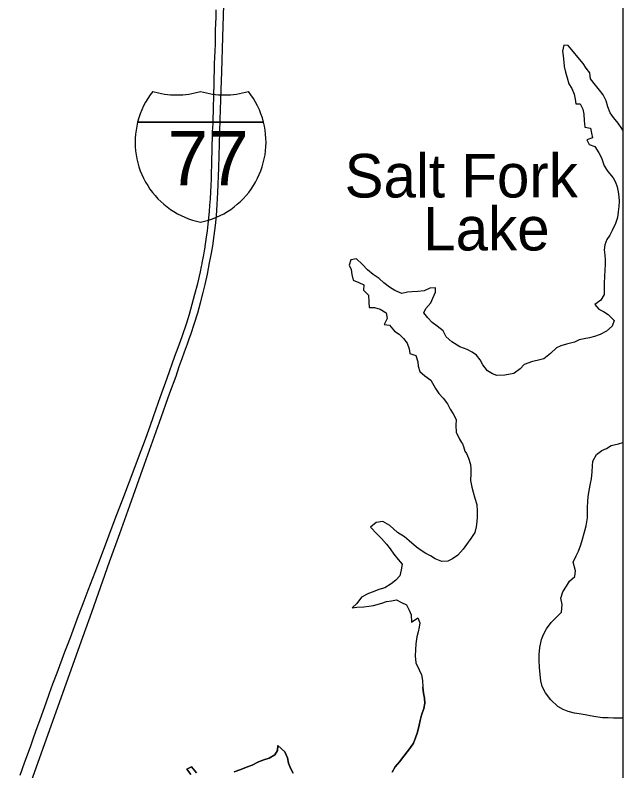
# Model space of a CAD drawing. Extents: x -12.1 to 34, y 0 to 22.
# Drawn here: x -5.676 to -4.438, y 15.867 to 17.405 of the extents above; entities that cross this region are included whole.
import ezdxf

# ---------------------------------------------------------------- set-up
doc = ezdxf.new("R2010")
doc.units = 0
for name, color, linetype in [('GM_X_Interstate_Route', 7, 'Continuous'), ('GM_X_Interstate_Shield', 7, 'Continuous'), ('GM_X_Major_Lake', 7, 'Continuous'), ('GM_X_Major_Lake_Text', 7, 'Continuous'), ('SH_Text', 7, 'Continuous')]:
    doc.layers.add(name, color=color, linetype=linetype)

msp = doc.modelspace()

# ---------------------------------------------------------------- linework, layer by layer
at = {"layer": 'GM_X_Interstate_Route'}
for points in [[(-5.6699, 15.7681), (-5.5912, 15.9891), (-5.5378, 16.1389), (-5.5195, 16.1898), (-5.4833, 16.2919), (-5.4626, 16.3494), (-5.4421, 16.407), (-5.4123, 16.491), (-5.3814, 16.5764), (-5.3605, 16.6357), (-5.3481, 16.6702), (-5.3414, 16.6895), (-5.3354, 16.7059), (-5.3306, 16.7197), (-5.3249, 16.7355), (-5.3213, 16.7457), (-5.3182, 16.7548), (-5.3105, 16.778), (-5.304, 16.7991), (-5.2982, 16.8193), (-5.2928, 16.8401), (-5.2889, 16.8565), (-5.2843, 16.8776), (-5.2797, 16.9004), (-5.2759, 16.9204), (-5.2734, 16.9353), (-5.2703, 16.956), (-5.2678, 16.9762), (-5.2658, 16.9965), (-5.264, 17.0191), (-5.2627, 17.0435), (-5.2608, 17.0936), (-5.2579, 17.1913), (-5.256, 17.2525), (-5.255, 17.2891), (-5.2531, 17.3601), (-5.251, 17.4259)], [(-5.6651, 15.8581), (-5.6563, 15.8828), (-5.6496, 15.9014), (-5.6445, 15.9157), (-5.6387, 15.9321), (-5.6332, 15.9475), (-5.6248, 15.971), (-5.6127, 16.005), (-5.6056, 16.0248), (-5.5987, 16.0439), (-5.5904, 16.0663), (-5.5742, 16.1087), (-5.5692, 16.1223), (-5.5632, 16.1381), (-5.5577, 16.1529), (-5.5464, 16.1828), (-5.5404, 16.1986), (-5.5351, 16.2128), (-5.5268, 16.2345), (-5.5129, 16.271), (-5.5, 16.3047), (-5.4847, 16.3449), (-5.4718, 16.3793), (-5.4546, 16.425), (-5.4332, 16.4807), (-5.4222, 16.5097), (-5.4125, 16.5362), (-5.4009, 16.5678), (-5.3939, 16.5877), (-5.3794, 16.6288), (-5.3663, 16.6656), (-5.3502, 16.7105), (-5.3438, 16.7282), (-5.3357, 16.7509), (-5.3263, 16.7785), (-5.3206, 16.7963), (-5.3149, 16.8161), (-5.3096, 16.8368), (-5.3039, 16.8586), (-5.2986, 16.8823), (-5.2962, 16.8931), (-5.295, 16.8982), (-5.2946, 16.9005), (-5.2929, 16.9103), (-5.2916, 16.9171), (-5.2901, 16.9251), (-5.2896, 16.9286), (-5.2881, 16.9384), (-5.2859, 16.9528), (-5.2843, 16.9655), (-5.2827, 16.9789), (-5.2815, 16.9922), (-5.2802, 17.005), (-5.2793, 17.0172), (-5.2782, 17.0305), (-5.2773, 17.0451), (-5.2768, 17.0579), (-5.2761, 17.0718), (-5.2759, 17.0852), (-5.2753, 17.0986), (-5.2751, 17.1132), (-5.2745, 17.1259), (-5.2743, 17.1405), (-5.2737, 17.1539), (-5.2735, 17.1673), (-5.2727, 17.1835), (-5.2724, 17.1952), (-5.2721, 17.2091), (-5.2715, 17.2225), (-5.2713, 17.2336), (-5.2709, 17.247), (-5.2705, 17.2604), (-5.2702, 17.2772), (-5.2697, 17.2912), (-5.2695, 17.3057), (-5.2689, 17.3191), (-5.2686, 17.3319), (-5.268, 17.3459), (-5.2676, 17.3599), (-5.2674, 17.3733), (-5.2668, 17.3884), (-5.2667, 17.4), (-5.2662, 17.4157)]]:
    msp.add_lwpolyline(points, dxfattribs=at)
at = {"layer": 'GM_X_Interstate_Shield'}
for p, q in [((-5.4262, 17.1871), (-5.17, 17.1871)), ((-5.17, 17.1871), (-5.4262, 17.1871)), ((-5.17, 17.1871), (-5.4262, 17.1871))]:
    msp.add_line(p, q, dxfattribs=at)
for centre, start, end in [((-5.2648, 17.1463), 141.669, 165.8066), ((-5.3468, 17.4087), 253.0091, 286.9909), ((-5.2495, 17.4087), 253.0091, 286.9909), ((-5.3314, 17.1463), 14.1934, 38.331), ((-5.2648, 17.1463), 165.8066, 258.463), ((-5.3314, 17.1463), 281.537, 14.1934)]:
    msp.add_arc(centre, 0.1665, start, end, dxfattribs=at)
at = {"layer": 'GM_X_Major_Lake'}
for points in [[(-4.4383, 17.1708), (-4.4405, 17.1738), (-4.4481, 17.1848), (-4.4574, 17.1961), (-4.4642, 17.206), (-4.4689, 17.218), (-4.4722, 17.2301), (-4.4787, 17.2425), (-4.4859, 17.2521), (-4.4941, 17.2623), (-4.5042, 17.2747), (-4.5053, 17.2875), (-4.5132, 17.2967), (-4.5193, 17.3062), (-4.5301, 17.3189), (-4.5391, 17.3302), (-4.5495, 17.3426), (-4.5583, 17.3433), (-4.5611, 17.3311), (-4.5596, 17.3216), (-4.5584, 17.3088), (-4.5576, 17.2999), (-4.5554, 17.2889), (-4.5518, 17.2768), (-4.5481, 17.2651), (-4.5424, 17.2552), (-4.5373, 17.2435), (-4.5354, 17.2335), (-4.5343, 17.2243), (-4.5254, 17.224), (-4.5197, 17.213), (-4.5178, 17.2031), (-4.5173, 17.1899), (-4.5158, 17.1764), (-4.5044, 17.1747), (-4.5019, 17.1644), (-4.5004, 17.1548), (-4.5117, 17.1512), (-4.507, 17.1416), (-4.4956, 17.1371), (-4.4874, 17.1247), (-4.4816, 17.1141), (-4.4761, 17.0981), (-4.4689, 17.0864), (-4.4578, 17.0737), (-4.4535, 17.0645), (-4.4502, 17.0549), (-4.448, 17.045), (-4.4465, 17.035), (-4.4461, 17.0261), (-4.4464, 17.0155), (-4.4477, 17.0041), (-4.4494, 16.9927), (-4.4532, 16.9806), (-4.4598, 16.9663), (-4.4651, 16.957), (-4.471, 16.9481)], [(-4.471, 16.9481), (-4.4748, 16.9374), (-4.4762, 16.9267), (-4.475, 16.916), (-4.4746, 16.9068), (-4.4742, 16.8979), (-4.4751, 16.8858), (-4.4754, 16.8737), (-4.4767, 16.8587), (-4.4766, 16.8474), (-4.4761, 16.836), (-4.4835, 16.8249), (-4.4952, 16.8159), (-4.4873, 16.8064), (-4.4776, 16.8015), (-4.468, 16.7955), (-4.4562, 16.7835), (-4.46, 16.7714), (-4.4716, 16.7613), (-4.4844, 16.7548), (-4.4964, 16.7508), (-4.506, 16.7479), (-4.5173, 16.746), (-4.5272, 16.7438), (-4.5371, 16.7391), (-4.5531, 16.7351), (-4.5644, 16.7314), (-4.5736, 16.7274), (-4.5856, 16.7163), (-4.5994, 16.7052), (-4.6128, 16.7015), (-4.6224, 16.6997), (-4.6394, 16.6938), (-4.6471, 16.6849), (-4.6602, 16.6755), (-4.6786, 16.6718), (-4.6949, 16.671), (-4.7038, 16.6748), (-4.7138, 16.6808), (-4.7232, 16.6932), (-4.7289, 16.7031), (-4.7361, 16.7123), (-4.7454, 16.7186), (-4.755, 16.7239), (-4.7703, 16.7298), (-4.7867, 16.7396), (-4.7982, 16.7502), (-4.8043, 16.7619), (-4.8161, 16.7718), (-4.8265, 16.7792), (-4.8354, 16.7883), (-4.8437, 16.7989), (-4.8395, 16.8079), (-4.8296, 16.8193), (-4.8254, 16.8286), (-4.8199, 16.8407), (-4.8196, 16.85), (-4.8313, 16.8492), (-4.843, 16.8434), (-4.8557, 16.8422), (-4.8674, 16.8418), (-4.8767, 16.8406), (-4.8884, 16.8381), (-4.9026, 16.844), (-4.9133, 16.851), (-4.9251, 16.8598), (-4.9344, 16.8686), (-4.9465, 16.8771), (-4.958, 16.8866), (-4.9691, 16.8975), (-4.9805, 16.9085), (-4.9922, 16.9069), (-4.9953, 16.8959), (-4.9914, 16.8867), (-4.9899, 16.8771), (-4.9873, 16.865), (-4.9762, 16.8608), (-4.9659, 16.8559), (-4.9662, 16.8446), (-4.9561, 16.835), (-4.9557, 16.8212), (-4.9549, 16.8094), (-4.9439, 16.8099), (-4.9328, 16.8061), (-4.92, 16.799), (-4.9185, 16.7873), (-4.9244, 16.7748), (-4.9138, 16.7738), (-4.9034, 16.7618), (-4.8941, 16.7555), (-4.8851, 16.7463), (-4.8772, 16.7368), (-4.8736, 16.7254), (-4.8721, 16.7158), (-4.8596, 16.712), (-4.8556, 16.6993), (-4.8552, 16.69), (-4.8516, 16.6797), (-4.8416, 16.6709), (-4.8291, 16.6618), (-4.8199, 16.6448)], [(-4.8199, 16.6448), (-4.8131, 16.6349), (-4.8045, 16.6253), (-4.7956, 16.6133), (-4.7899, 16.6027), (-4.7841, 16.5932), (-4.778, 16.5815), (-4.7783, 16.5694), (-4.7779, 16.5559), (-4.7707, 16.5414), (-4.7671, 16.535), (-4.7646, 16.5322), (-4.7631, 16.5265), (-4.7599, 16.5173), (-4.7567, 16.5127), (-4.7523, 16.5028), (-4.7487, 16.4904), (-4.7479, 16.4812), (-4.7482, 16.4716), (-4.7485, 16.4574), (-4.7456, 16.4443), (-4.743, 16.434), (-4.7398, 16.4219), (-4.7358, 16.4088), (-4.7353, 16.3953), (-4.7352, 16.3836), (-4.7355, 16.3736), (-4.7369, 16.363), (-4.74, 16.3519), (-4.7481, 16.3394), (-4.7565, 16.3273), (-4.7635, 16.3177), (-4.7741, 16.3059), (-4.785, 16.298), (-4.7949, 16.2933), (-4.8069, 16.2928), (-4.8204, 16.2984), (-4.83, 16.3044), (-4.8393, 16.3089), (-4.8492, 16.3153), (-4.8585, 16.3216), (-4.8735, 16.335), (-4.8831, 16.3431), (-4.8973, 16.3515), (-4.9126, 16.3663), (-4.9269, 16.374), (-4.9403, 16.3721), (-4.9519, 16.3625), (-4.9395, 16.3491), (-4.9298, 16.3395), (-4.9198, 16.3279), (-4.912, 16.3184), (-4.9048, 16.3074), (-4.8955, 16.2965), (-4.8877, 16.2873), (-4.8894, 16.2755), (-4.8921, 16.2638), (-4.9009, 16.2549), (-4.9104, 16.247), (-4.9228, 16.2394), (-4.9352, 16.2354), (-4.9468, 16.2311), (-4.9564, 16.2274), (-4.9708, 16.2202), (-4.9803, 16.2074), (-4.9898, 16.1984), (-4.9799, 16.1999), (-4.9657, 16.2004), (-4.9555, 16.2015), (-4.9463, 16.203), (-4.9293, 16.2078), (-4.9194, 16.2114), (-4.9091, 16.2125), (-4.8992, 16.2147), (-4.8889, 16.2095), (-4.8786, 16.2046), (-4.8732, 16.1936), (-4.8696, 16.184), (-4.8685, 16.1691), (-4.8561, 16.1781), (-4.8518, 16.1678), (-4.8532, 16.1589), (-4.8552, 16.1493), (-4.8576, 16.1394), (-4.8597, 16.1248), (-4.8606, 16.1131), (-4.8613, 16.101), (-4.8598, 16.0868), (-4.8533, 16.0723), (-4.8486, 16.0623), (-4.8464, 16.0506), (-4.8456, 16.0368)], [(-4.4383, 15.9737), (-4.4484, 15.9739), (-4.4576, 15.9739), (-4.4682, 15.9745), (-4.4795, 15.9748), (-4.4937, 15.9768), (-4.5047, 15.9789), (-4.515, 15.9809), (-4.5271, 15.9826), (-4.5366, 15.984), (-4.5498, 15.9871), (-4.5601, 15.9913), (-4.5707, 15.9976), (-4.5847, 16.011), (-4.5957, 16.0251), (-4.6029, 16.0382), (-4.6051, 16.0499), (-4.6078, 16.0762), (-4.6089, 16.0929), (-4.6087, 16.1032), (-4.6073, 16.1177), (-4.6039, 16.1341), (-4.5997, 16.1444), (-4.5938, 16.1555), (-4.5846, 16.1687), (-4.5741, 16.1787), (-4.5632, 16.1898), (-4.5622, 16.2051), (-4.5648, 16.2179), (-4.5606, 16.2307), (-4.5533, 16.2424), (-4.5469, 16.2524), (-4.536, 16.2625), (-4.5347, 16.2735), (-4.5394, 16.2912), (-4.5331, 16.3044), (-4.5289, 16.3137), (-4.5237, 16.3269), (-4.5206, 16.3382), (-4.5171, 16.3507), (-4.5133, 16.3653), (-4.5106, 16.3813), (-4.5103, 16.3916), (-4.5104, 16.4019), (-4.5098, 16.4154), (-4.5091, 16.4246), (-4.5071, 16.4374), (-4.5043, 16.4513), (-4.5023, 16.4609), (-4.5009, 16.4751), (-4.5003, 16.4872), (-4.4997, 16.4968), (-4.4923, 16.5104), (-4.4814, 16.5186), (-4.4719, 16.5226), (-4.462, 16.5287), (-4.4471, 16.5324), (-4.4383, 16.5352)], [(-4.8456, 16.0368), (-4.8441, 16.0244), (-4.8419, 16.0144), (-4.8415, 16.0041), (-4.8439, 15.9938), (-4.8481, 15.9799), (-4.8508, 15.9693), (-4.8529, 15.9593), (-4.8563, 15.9451), (-4.8602, 15.9337), (-4.8647, 15.9233), (-4.871, 15.9144), (-4.8773, 15.9055), (-4.884, 15.8965), (-4.8931, 15.8851), (-4.9019, 15.8751), (-4.9082, 15.8637)], [(-4.9082, 15.8637), (-4.9019, 15.8751), (-4.8931, 15.8851), (-4.884, 15.8965), (-4.8773, 15.9055), (-4.871, 15.9144), (-4.8647, 15.9233), (-4.8602, 15.9337), (-4.8563, 15.9451), (-4.8529, 15.9593), (-4.8508, 15.9693), (-4.8481, 15.9799), (-4.8439, 15.9938), (-4.8415, 16.0041), (-4.8419, 16.0144), (-4.8441, 16.0244), (-4.8456, 16.0368)], [(-5.1098, 15.8622), (-5.1152, 15.8724), (-5.1192, 15.8824), (-5.1214, 15.893), (-5.1268, 15.9054), (-5.141, 15.9184), (-5.1413, 15.9078), (-5.1466, 15.8989), (-5.1582, 15.8927), (-5.1695, 15.8891), (-5.1805, 15.8851), (-5.1932, 15.8783), (-5.2048, 15.8739), (-5.2162, 15.8696), (-5.2299, 15.8648)], [(-5.2299, 15.8648), (-5.2162, 15.8696), (-5.2048, 15.8739), (-5.1932, 15.8783), (-5.1805, 15.8851), (-5.1695, 15.8891), (-5.1582, 15.8927), (-5.1466, 15.8989), (-5.1413, 15.9078), (-5.141, 15.9184), (-5.1268, 15.9054), (-5.1214, 15.893), (-5.1192, 15.8824), (-5.1152, 15.8724), (-5.1098, 15.8622)], [(-5.3061, 15.8628), (-5.3165, 15.8748), (-5.3263, 15.8698), (-5.3181, 15.8595)], [(-5.3181, 15.8595), (-5.3263, 15.8698), (-5.3165, 15.8748), (-5.3061, 15.8628)]]:
    msp.add_lwpolyline(points, dxfattribs=at)
at = {"layer": 'SH_Text'}
msp.add_lwpolyline([(-12.1463, 20.3063), (-4.4383, 20.3063), (-4.4383, 10.9773), (-12.1463, 10.9773)], close=True, dxfattribs=at)

# ---------------------------------------------------------------- texts
at = {"layer": 'GM_X_Interstate_Shield'}
msp.add_text('77', height=0.11097, dxfattribs=at).set_placement((-5.3655, 17.0581))
at = {"layer": 'GM_X_Major_Lake_Text'}
for s, rotation, p in [('Salt Fork', 0.0035, (-5.0048, 17.0335)), ('Lake', 0.0018, (-4.8448, 16.9257))]:
    msp.add_text(s, height=0.08878, rotation=rotation, dxfattribs=at).set_placement(p)

doc.saveas('drawing.dxf')
